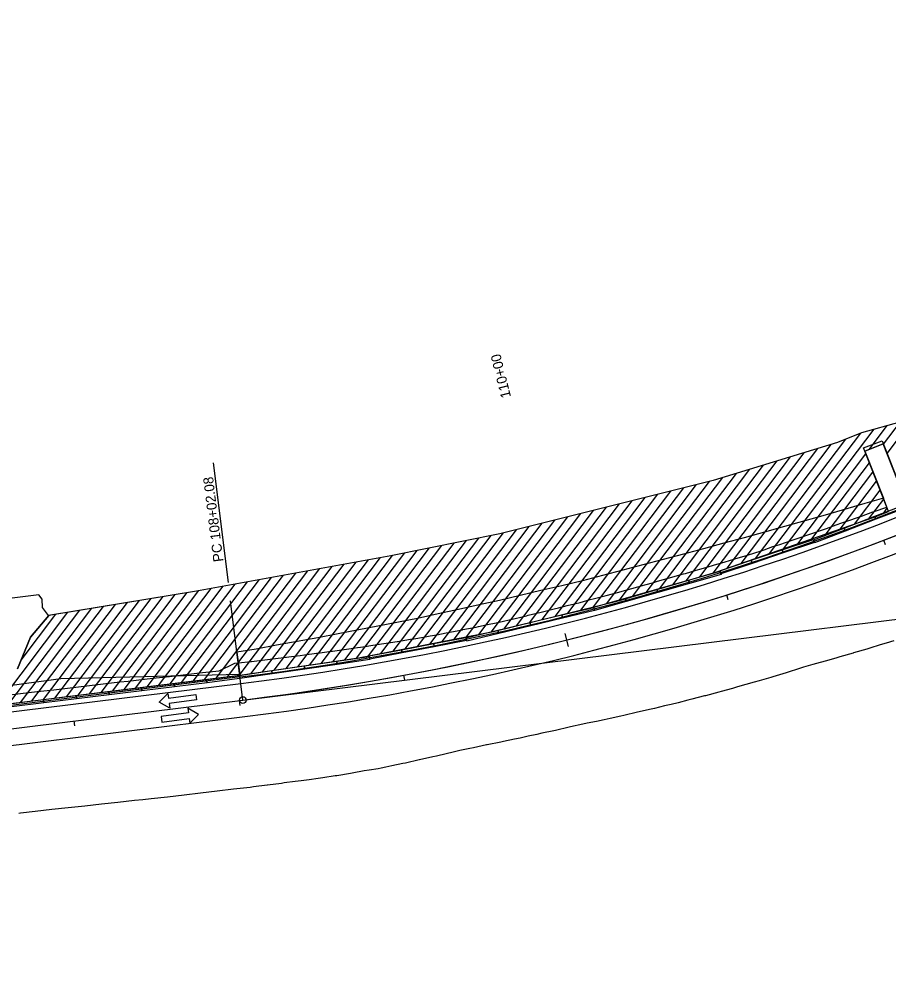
# Model space of a CAD drawing. Extents: x 1568809 to 1572786, y 728326 to 734907.
# Drawn here: x 1570948 to 1571471, y 732119 to 732690 of the extents above; entities that cross this region are included whole.
import ezdxf

# ---------------------------------------------------------------- set-up
doc = ezdxf.new("R2010")
doc.units = 0
for name, color, linetype in [('R_Horz Alg', 7, 'Continuous'), ('R_Horz Alg Annot', 7, 'Continuous'), ('R_MOT', 7, 'Continuous'), ('R_No Plot', 7, 'Continuous'), ('R_Striping', 7, 'Continuous')]:
    doc.layers.add(name, color=color, linetype=linetype)

msp = doc.modelspace()

# ---------------------------------------------------------------- linework, layer by layer
at = {"layer": 'R_Horz Alg'}
msp.add_line((1569774.69, 732119.01), (1571082.41, 732280.73), dxfattribs=at)
msp.add_arc((1570881.49, 733905.38), 1637.02, 277.05, 312.07494, dxfattribs=at)
at = {"layer": 'R_Horz Alg Annot'}
msp.add_line((1571082.41, 732280.73), (1571564.61, 732340.37), dxfattribs=at)
for points in [[(1571073.68, 732351.37), (1571064.76, 732423.44)], [(1571468.61, 732374.05), (1571467.54, 732376.85)], [(1571082.41, 732280.73), (1571075.04, 732340.32)], [(1571374.03, 732341.07), (1571373.13, 732343.93)], [(1571275.93, 732320.71), (1571277.86, 732312.94)], [(1571179.72, 732292.7), (1571179.18, 732295.65)], [(1571080.72, 732277.5), (1571080.35, 732280.48)], [(1570981.47, 732265.23), (1570981.1, 732268.21)]]:
    msp.add_lwpolyline(points, dxfattribs=at)
msp.add_circle((1571082.41, 732280.73), 2, dxfattribs=at)
at = {"layer": 'R_MOT'}
for p, q in [((1571469.54, 732429.06), (1571485.54, 732450.2)), ((1571407.38, 732371.74), (1571461.7, 732443.55)), ((1571458.88, 732431.54), (1571469.64, 732445.77)), ((1571467.4, 732434.51), (1571477.59, 732447.98)), ((1571390.38, 732365.85), (1571444.65, 732437.59)), ((1571398.88, 732368.8), (1571453.69, 732441.25)), ((1571373.38, 732359.95), (1571427.87, 732431.98)), ((1571381.88, 732362.9), (1571436.02, 732434.47)), ((1571356.91, 732354.76), (1571411.56, 732427)), ((1571364.96, 732357.12), (1571419.71, 732429.49)), ((1571415.88, 732374.69), (1571456.77, 732428.75)), ((1571340.8, 732350.03), (1571395.26, 732422.03)), ((1571348.85, 732352.4), (1571403.41, 732424.52)), ((1571424.38, 732377.64), (1571458.92, 732423.3)), ((1571316.63, 732342.95), (1571370.8, 732414.56)), ((1571324.69, 732345.31), (1571378.96, 732417.05)), ((1571332.74, 732347.67), (1571387.11, 732419.54)), ((1571432.88, 732380.59), (1571461.06, 732417.85)), ((1571293.16, 732336.78), (1571347.31, 732408.36)), ((1571300.87, 732338.69), (1571355.04, 732410.3)), ((1571308.58, 732340.6), (1571362.77, 732412.24)), ((1571441.38, 732383.54), (1571463.21, 732412.4)), ((1571270.02, 732331.06), (1571324.1, 732402.55)), ((1571277.73, 732332.97), (1571331.84, 732404.49)), ((1571285.44, 732334.88), (1571339.57, 732406.43)), ((1571449.88, 732386.48), (1571465.36, 732406.95)), ((1571254.59, 732327.25), (1571308.63, 732398.68)), ((1571262.31, 732329.15), (1571316.37, 732400.62)), ((1571458.38, 732389.43), (1571467.5, 732401.5)), ((1571231.52, 732321.61), (1571285.43, 732392.87)), ((1571239.17, 732323.43), (1571293.16, 732394.81)), ((1571246.88, 732325.34), (1571300.9, 732396.74)), ((1571467.15, 732392.75), (1571469.65, 732396.05)), ((1571209.45, 732317.3), (1571262.22, 732387.06)), ((1571216.81, 732318.74), (1571269.96, 732389)), ((1571224.17, 732320.17), (1571277.69, 732390.93)), ((1571187.38, 732312.99), (1571239.02, 732381.25)), ((1571194.74, 732314.43), (1571246.75, 732383.19)), ((1571202.1, 732315.86), (1571254.49, 732385.12)), ((1571157.95, 732307.24), (1571209.34, 732375.17)), ((1571165.31, 732308.68), (1571216.74, 732376.66)), ((1571172.67, 732310.11), (1571224.13, 732378.15)), ((1571180.02, 732311.55), (1571231.53, 732379.64)), ((1571129.5, 732302.78), (1571179.76, 732369.22)), ((1571136.55, 732303.81), (1571187.16, 732370.7)), ((1571143.6, 732304.84), (1571194.55, 732372.19)), ((1571150.65, 732305.87), (1571201.95, 732373.68)), ((1571101.3, 732298.65), (1571150.54, 732363.73)), ((1571108.35, 732299.69), (1571157.81, 732365.06)), ((1571115.4, 732300.72), (1571165.08, 732366.38)), ((1571122.45, 732301.75), (1571172.37, 732367.73)), ((1571066.33, 732293.86), (1571114.19, 732357.12)), ((1571073.25, 732294.71), (1571121.46, 732358.44)), ((1571080.16, 732295.57), (1571128.73, 732359.77)), ((1571087.2, 732296.59), (1571136, 732361.09)), ((1571094.25, 732297.62), (1571143.27, 732362.41)), ((1571038.66, 732290.44), (1571085.1, 732351.83)), ((1571045.58, 732291.29), (1571092.37, 732353.15)), ((1571052.5, 732292.15), (1571099.64, 732354.47)), ((1571059.41, 732293), (1571106.91, 732355.8)), ((1571011, 732287.02), (1571056.02, 732346.54)), ((1571017.91, 732287.87), (1571063.29, 732347.86)), ((1571024.83, 732288.73), (1571070.56, 732349.18)), ((1571031.75, 732289.58), (1571077.83, 732350.51)), ((1570976.41, 732282.74), (1571020.19, 732340.61)), ((1570983.33, 732283.59), (1571027.36, 732341.79)), ((1570990.25, 732284.45), (1571034.52, 732342.97)), ((1570997.16, 732285.31), (1571041.68, 732344.15)), ((1571004.08, 732286.16), (1571048.84, 732345.33)), ((1570941.83, 732278.46), (1570984.39, 732334.72)), ((1570948.75, 732279.32), (1570991.55, 732335.9)), ((1570955.66, 732280.17), (1570998.71, 732337.08)), ((1570962.58, 732281.03), (1571005.87, 732338.26)), ((1570969.5, 732281.88), (1571013.03, 732339.43)), ((1570934.91, 732277.61), (1570977.23, 732333.54)), ((1570949.11, 732304.66), (1570970.06, 732332.36)), ((1571080.69, 732294.63), (1571001.94, 732284.89))]:
    msp.add_line(p, q, dxfattribs=at)
for points in [[(1571462.16, 732391.27), (1571480.59, 732398.36), (1571481.3, 732396.52), (1571462.86, 732389.43)], [(1571443.72, 732384.18), (1571462.16, 732391.27), (1571462.86, 732389.43), (1571444.43, 732382.33)], [(1571425.29, 732377.09), (1571443.72, 732384.18), (1571444.43, 732382.33), (1571426, 732375.24)], [(1571406.53, 732371.05), (1571425.26, 732377.32), (1571425.88, 732375.45), (1571407.15, 732369.18)], [(1571387.8, 732364.79), (1571406.53, 732371.05), (1571407.15, 732369.18), (1571388.43, 732362.91)], [(1571369.07, 732358.52), (1571387.8, 732364.79), (1571388.43, 732362.91), (1571369.7, 732356.65)], [(1571350.22, 732352.78), (1571369.21, 732358.21), (1571369.76, 732356.31), (1571350.77, 732350.88)], [(1571331.24, 732347.35), (1571350.22, 732352.78), (1571350.77, 732350.88), (1571331.78, 732345.45)], [(1571312.25, 732341.92), (1571331.24, 732347.35), (1571331.78, 732345.45), (1571312.79, 732340.03)], [(1571293.26, 732336.5), (1571312.25, 732341.92), (1571312.79, 732340.03), (1571293.8, 732334.6)], [(1571274.1, 732331.9), (1571293.31, 732336.48), (1571293.77, 732334.56), (1571274.56, 732329.98)], [(1571254.89, 732327.32), (1571274.1, 732331.9), (1571274.56, 732329.98), (1571255.35, 732325.4)], [(1571216.47, 732318.16), (1571235.68, 732322.74), (1571236.14, 732320.82), (1571216.93, 732316.24)], [(1571235.68, 732322.74), (1571254.89, 732327.32), (1571255.35, 732325.4), (1571236.14, 732320.82)], [(1571197.06, 732314.71), (1571216.45, 732318.44), (1571216.83, 732316.5), (1571197.43, 732312.77)], [(1571177.67, 732310.99), (1571197.06, 732314.71), (1571197.43, 732312.77), (1571178.04, 732309.05)], [(1571138.82, 732304.13), (1571158.36, 732306.99), (1571158.65, 732305.03), (1571139.11, 732302.17)], [(1571158.27, 732307.27), (1571177.67, 732310.99), (1571178.04, 732309.05), (1571158.64, 732305.33)], [(1571099.74, 732298.41), (1571119.28, 732301.27), (1571119.57, 732299.32), (1571100.03, 732296.46)], [(1571119.28, 732301.27), (1571138.82, 732304.13), (1571139.11, 732302.17), (1571119.57, 732299.32)], [(1571060.62, 732293.14), (1571080.22, 732295.56), (1571080.46, 732293.6), (1571060.86, 732291.18)], [(1571080.2, 732295.55), (1571099.74, 732298.41), (1571100.03, 732296.46), (1571080.49, 732293.6)], [(1571001.82, 732285.87), (1571021.42, 732288.29), (1571021.67, 732286.33), (1571002.07, 732283.91)], [(1571021.42, 732288.29), (1571041.02, 732290.72), (1571041.26, 732288.76), (1571021.67, 732286.33)], [(1571041.02, 732290.72), (1571060.62, 732293.14), (1571060.86, 732291.18), (1571041.26, 732288.76)], [(1570962.63, 732281.02), (1570982.23, 732283.44), (1570982.47, 732281.48), (1570962.87, 732279.06)], [(1570982.23, 732283.44), (1571001.83, 732285.87), (1571002.07, 732283.91), (1570982.47, 732281.48)], [(1571038.5, 732275.8), (1571032.11, 732279.48), (1571037.3, 732284.72), (1571037.67, 732281.93), (1571054.07, 732284.15), (1571054.53, 732280.8), (1571038.12, 732278.59)], [(1570943.03, 732278.6), (1570962.63, 732281.02), (1570962.87, 732279.06), (1570943.27, 732276.64)], [(1571050.51, 732266.9), (1571055.7, 732272.14), (1571049.3, 732275.82), (1571049.68, 732273.03), (1571033.28, 732270.82), (1571033.73, 732267.48), (1571050.13, 732269.69)]]:
    msp.add_lwpolyline(points, close=True, dxfattribs=at)
msp.add_arc((1570881.49, 733905.38), 1623.02, 277.05, 292.35853, dxfattribs=at)
at = {"layer": 'R_No Plot'}
for p, q in [((1570959.69, 732344.02), (1570943.76, 732342.05)), ((1570959.69, 732344.02), (1570943.76, 732342.05)), ((1570965.58, 732331.62), (1570961.92, 732336.37)), ((1570965.58, 732331.62), (1570961.92, 732336.37)), ((1571078.82, 732309.53), (1571080.52, 732296.05)), ((1571078.82, 732309.53), (1571080.52, 732296.05)), ((1571080.69, 732294.63), (1571069.63, 732293.26)), ((1571069.63, 732293.26), (1570994.16, 732283.92)), ((1570994.16, 732283.92), (1570920.86, 732274.74))]:
    msp.add_line(p, q, dxfattribs=at)
for points in [[(1571636.54, 732496.83), (1571569.31, 732473.57), (1571454.21, 732441.46)], [(1571636.54, 732496.83), (1571569.31, 732473.57), (1571454.21, 732441.46)], [(1571636.54, 732496.83), (1571569.31, 732473.57), (1571454.21, 732441.46)], [(1571454.21, 732441.46), (1571439.77, 732435.61), (1571365.05, 732412.81), (1571236.87, 732380.71), (1571171.22, 732367.5), (1571054.49, 732346.26), (1570965.58, 732331.62)], [(1571454.21, 732441.46), (1571439.77, 732435.61), (1571365.05, 732412.81), (1571236.87, 732380.71), (1571171.22, 732367.5), (1571054.49, 732346.26), (1570965.58, 732331.62)], [(1571454.21, 732441.46), (1571439.77, 732435.61), (1571365.05, 732412.81), (1571236.87, 732380.71), (1571171.22, 732367.5), (1571054.49, 732346.26), (1570965.7, 732331.64)], [(1571478.88, 732405.37), (1571467.27, 732434.84), (1571456.1, 732430.44), (1571467.29, 732402.04), (1571456.21, 732398.85), (1571432.22, 732391.94), (1571420.08, 732388.52), (1571407.95, 732385.1), (1571395.82, 732381.68), (1571383.68, 732378.26), (1571371.49, 732375.01), (1571359.3, 732371.75), (1571347.11, 732368.49), (1571334.93, 732365.24), (1571322.8, 732362.04), (1571310.67, 732358.84), (1571298.54, 732355.64), (1571286.41, 732352.44), (1571273.98, 732349.5), (1571261.55, 732346.56), (1571249.12, 732343.61), (1571236.69, 732340.67), (1571224.35, 732337.97), (1571212.01, 732335.27), (1571199.67, 732332.57), (1571187.33, 732329.87), (1571163.51, 732325.17), (1571139.68, 732320.46), (1571127.35, 732318.19), (1571115.01, 732315.92), (1571102.68, 732313.66), (1571090.34, 732311.39), (1571078.82, 732309.53)], [(1571478.88, 732405.37), (1571467.27, 732434.84), (1571456.1, 732430.44), (1571467.29, 732402.04), (1571456.21, 732398.85), (1571432.22, 732391.94), (1571420.08, 732388.52), (1571407.95, 732385.1), (1571395.82, 732381.68), (1571383.68, 732378.26), (1571371.49, 732375.01), (1571359.3, 732371.75), (1571347.11, 732368.49), (1571334.93, 732365.24), (1571322.8, 732362.04), (1571310.67, 732358.84), (1571298.54, 732355.64), (1571286.41, 732352.44), (1571273.98, 732349.5), (1571261.55, 732346.56), (1571249.12, 732343.61), (1571236.69, 732340.67), (1571224.35, 732337.97), (1571212.01, 732335.27), (1571199.67, 732332.57), (1571187.33, 732329.87), (1571163.51, 732325.17), (1571139.68, 732320.46), (1571127.35, 732318.19), (1571115.01, 732315.92), (1571102.68, 732313.66), (1571090.34, 732311.39), (1571078.82, 732309.53)], [(1571080.57, 732295.62), (1571151.93, 732306.06), (1571232.93, 732321.89), (1571308.73, 732340.63), (1571366.54, 732357.58), (1571461.79, 732390.62), (1571470.44, 732394.06), (1571467.29, 732402.04), (1571456.1, 732430.44), (1571467.27, 732434.84), (1571478.88, 732405.37), (1571481.6, 732398.45), (1571540.52, 732423.79), (1571576.03, 732435.15)], [(1571080.57, 732295.62), (1571151.93, 732306.06), (1571232.93, 732321.89), (1571308.73, 732340.63), (1571366.54, 732357.58), (1571461.79, 732390.62), (1571470.44, 732394.06), (1571467.29, 732402.04), (1571456.1, 732430.44), (1571467.27, 732434.84), (1571478.88, 732405.37), (1571481.6, 732398.45), (1571540.52, 732423.79), (1571576.03, 732435.15)], [(1571080.57, 732295.62), (1571151.93, 732306.06), (1571232.93, 732321.89), (1571308.73, 732340.63), (1571366.54, 732357.58), (1571461.79, 732390.62), (1571470.44, 732394.06), (1571467.29, 732402.04), (1571456.1, 732430.44), (1571467.27, 732434.84), (1571478.88, 732405.37), (1571481.6, 732398.45), (1571540.52, 732423.79), (1571576.03, 732435.15)], [(1571469.37, 732396.77), (1571455.37, 732432.3), (1571466.53, 732436.7), (1571478.88, 732405.37), (1571492.28, 732409.3), (1571504.36, 732412.85), (1571516.43, 732416.4), (1571528.51, 732419.94), (1571540.52, 732423.79), (1571576.03, 732435.15)], [(1570938.9, 732283.55), (1570948.84, 732284.68), (1570958.78, 732285.81), (1570968.71, 732286.97), (1570978.64, 732288.14), (1570988.57, 732289.32), (1570998.5, 732290.47), (1571008.44, 732291.6), (1571013.38, 732292.16), (1571018.38, 732292.72), (1571028.31, 732293.86), (1571038.25, 732294.97), (1571048.18, 732296.13), (1571058.12, 732297.26), (1571068.06, 732298.4), (1571077.58, 732302.86), (1571079.65, 732303.08), (1571087.41, 732303.96), (1571087.62, 732303.98), (1571095.59, 732304.92), (1571097.21, 732305.11), (1571103.56, 732305.88), (1571107, 732306.31), (1571111.53, 732306.88), (1571116.79, 732307.54), (1571119.49, 732307.89), (1571126.57, 732308.84), (1571127.45, 732308.96), (1571135.4, 732310.05), (1571136.35, 732310.18), (1571143.35, 732311.17), (1571146.12, 732311.56), (1571151.3, 732312.32), (1571153.04, 732312.58), (1571155.89, 732313.01), (1571159.24, 732313.52), (1571165.66, 732314.44), (1571167.2, 732314.68), (1571175.13, 732315.97), (1571175.41, 732316.01), (1571183.05, 732317.29), (1571185.15, 732317.62), (1571190.99, 732318.57), (1571194.89, 732319.31), (1571198.89, 732320.04), (1571204.6, 732321.11), (1571206.78, 732321.53), (1571214.29, 732323.02), (1571214.67, 732323.09), (1571222.55, 732324.66), (1571223.98, 732324.96), (1571230.41, 732326.31), (1571233.65, 732326.99), (1571238.27, 732327.99), (1571243.29, 732329.13), (1571246.11, 732329.77), (1571252.9, 732331.44), (1571253.92, 732331.68), (1571261.74, 732333.56), (1571262.5, 732333.76), (1571269.53, 732335.51), (1571272.08, 732336.14), (1571277.32, 732337.52), (1571281.65, 732338.61), (1571285.11, 732339.49), (1571291.2, 732341.13), (1571292.87, 732341.57), (1571300.64, 732343.62), (1571300.75, 732343.65), (1571308.4, 732345.7), (1571310.29, 732346.22), (1571316.15, 732347.82), (1571319.82, 732348.83), (1571323.9, 732349.96), (1571329.33, 732351.48), (1571331.64, 732352.13), (1571338.83, 732354.19), (1571339.37, 732354.34), (1571347.09, 732356.57), (1571348.33, 732356.92), (1571354.83, 732358.76), (1571357.84, 732359.61), (1571362.55, 732360.99), (1571367.31, 732362.43), (1571370.25, 732363.31), (1571376.79, 732365.23), (1571377.96, 732365.58), (1571385.67, 732367.89), (1571386.25, 732368.08), (1571393.33, 732370.34), (1571395.65, 732371.16), (1571400.93, 732372.97), (1571405.02, 732374.3), (1571408.57, 732375.48), (1571414.36, 732377.52), (1571416.17, 732378.11), (1571423.7, 732380.76), (1571423.75, 732380.78), (1571431.38, 732383.34), (1571433.08, 732383.88), (1571438.95, 732386.05), (1571442.39, 732387.22), (1571446.57, 732388.65), (1571451.74, 732390.45), (1571454.13, 732391.4), (1571461.02, 732393.85), (1571461.71, 732394.09), (1571469.37, 732396.77)], [(1570961.92, 732336.37), (1570961.87, 732341.4), (1570959.69, 732344.02)], [(1570961.92, 732336.37), (1570961.87, 732341.4), (1570959.69, 732344.02)], [(1570947.01, 732299.46), (1570954.72, 732318.58), (1570965.7, 732331.64)], [(1570965.7, 732331.64), (1570954.72, 732318.58), (1570947.01, 732299.46)], [(1571473.49, 732316.39), (1571469.07, 732315.01), (1571465.43, 732313.88), (1571459.15, 732311.97), (1571457.36, 732311.43), (1571449.27, 732309.03), (1571449.22, 732309.01), (1571441.18, 732306.67), (1571439.26, 732306.13), (1571433.06, 732304.38), (1571429.28, 732303.33), (1571424.94, 732302.14), (1571419.32, 732300.5), (1571416.87, 732299.72), (1571409.46, 732297.39), (1571408.85, 732297.2), (1571400.8, 732294.77), (1571399.57, 732294.39), (1571392.74, 732292.36), (1571389.66, 732291.45), (1571384.65, 732290.05), (1571379.71, 732288.63), (1571376.56, 732287.74), (1571369.75, 732285.85), (1571368.44, 732285.55), (1571360.32, 732283.35), (1571359.76, 732283.2), (1571352.19, 732281.2), (1571349.77, 732280.57), (1571344.04, 732279.16), (1571339.73, 732278.11), (1571335.86, 732277.19), (1571329.68, 732275.7), (1571327.69, 732275.23), (1571319.61, 732273.39), (1571319.49, 732273.36), (1571311.3, 732271.5), (1571309.54, 732271.11), (1571303.09, 732269.71), (1571299.45, 732268.89), (1571294.89, 732267.91), (1571289.36, 732266.75), (1571286.67, 732266.19), (1571279.28, 732264.53), (1571278.48, 732264.34), (1571270.3, 732262.46), (1571269.23, 732262.21), (1571262.08, 732260.78), (1571259.13, 732260.11), (1571253.89, 732258.95), (1571249.06, 732257.89), (1571245.68, 732257.23), (1571238.97, 732255.78), (1571237.48, 732255.46), (1571229.26, 732253.79), (1571228.87, 732253.71), (1571221.05, 732252.08), (1571218.77, 732251.61), (1571212.83, 732250.4), (1571208.69, 732249.45), (1571204.66, 732248.47), (1571198.66, 732247.03), (1571196.49, 732246.51), (1571188.58, 732244.79), (1571188.29, 732244.72), (1571180.1, 732242.85), (1571178.51, 732242.49), (1571171.86, 732241.2), (1571168.39, 732240.44), (1571165.45, 732239.8), (1571163.64, 732239.46), (1571158.25, 732238.51), (1571155.36, 732238.08), (1571148.08, 732236.77), (1571147.09, 732236.59), (1571138.81, 732235.2), (1571137.9, 732235.07), (1571130.5, 732234.01), (1571127.68, 732233.58), (1571122.18, 732232.83), (1571117.45, 732232.2), (1571113.86, 732231.73), (1571107.22, 732230.86), (1571105.53, 732230.62), (1571097.2, 732229.55), (1571096.98, 732229.52), (1571088.87, 732228.49), (1571086.81, 732228.24), (1571076.87, 732227.1), (1571066.94, 732225.91), (1571057.02, 732224.69), (1571047.08, 732223.57), (1571037.15, 732222.42), (1571027.2, 732221.36), (1571022.21, 732220.82), (1571017.26, 732220.28), (1571007.32, 732219.18), (1570997.38, 732218.05), (1570987.43, 732217.02), (1570977.49, 732215.98), (1570967.55, 732214.87), (1570957.61, 732213.73), (1570948.82, 732212.71), (1570947.68, 732212.58)], [(1571080.52, 732296.05), (1570973.02, 732293.44), (1570943.63, 732289.39), (1570933.75, 732279.73), (1570896.54, 732272.86), (1570444.72, 732215.92), (1570444.57, 732216.97), (1570302.77, 732199.43)], [(1571080.52, 732296.05), (1570973.02, 732293.44), (1570943.63, 732289.39), (1570933.75, 732279.73), (1570896.54, 732272.86), (1570444.72, 732215.92), (1570444.57, 732216.97), (1570302.77, 732199.43)], [(1570896.54, 732272.86), (1570943.54, 732278.67), (1570975.29, 732282.6), (1571080.57, 732295.62)], [(1570896.54, 732272.86), (1570943.54, 732278.67), (1570975.29, 732282.6), (1571080.57, 732295.62)], [(1570896.54, 732272.86), (1570943.54, 732278.67), (1570975.29, 732282.6), (1571080.57, 732295.62)]]:
    msp.add_lwpolyline(points, dxfattribs=at)
msp.add_arc((1570881.49, 733905.38), 1623.02, 277.05, 292.35853, dxfattribs=at)
at = {"layer": 'R_Striping'}
for p, q in [((1570027.14, 732160.3), (1571081.18, 732290.66)), ((1570028.36, 732150.38), (1571082.41, 732280.73)), ((1570029.59, 732140.45), (1571083.64, 732270.81))]:
    msp.add_line(p, q, dxfattribs=at)
for radius, end in [(1637.02, 305.87703), (1627.02, 304.97724), (1647.02, 304.97724)]:
    msp.add_arc((1570881.49, 733905.38), radius, 277.05, end, dxfattribs=at)

# ---------------------------------------------------------------- texts
at = {"layer": 'R_Horz Alg Annot'}
for s, rotation, p in [('110+00', 103.9773, (1571243.57, 732463.11)), ('PC 108+02.08', 97.05, (1571070.73, 732364.17))]:
    msp.add_text(s, height=6, rotation=rotation, dxfattribs=at).set_placement(p)

doc.saveas('drawing.dxf')
